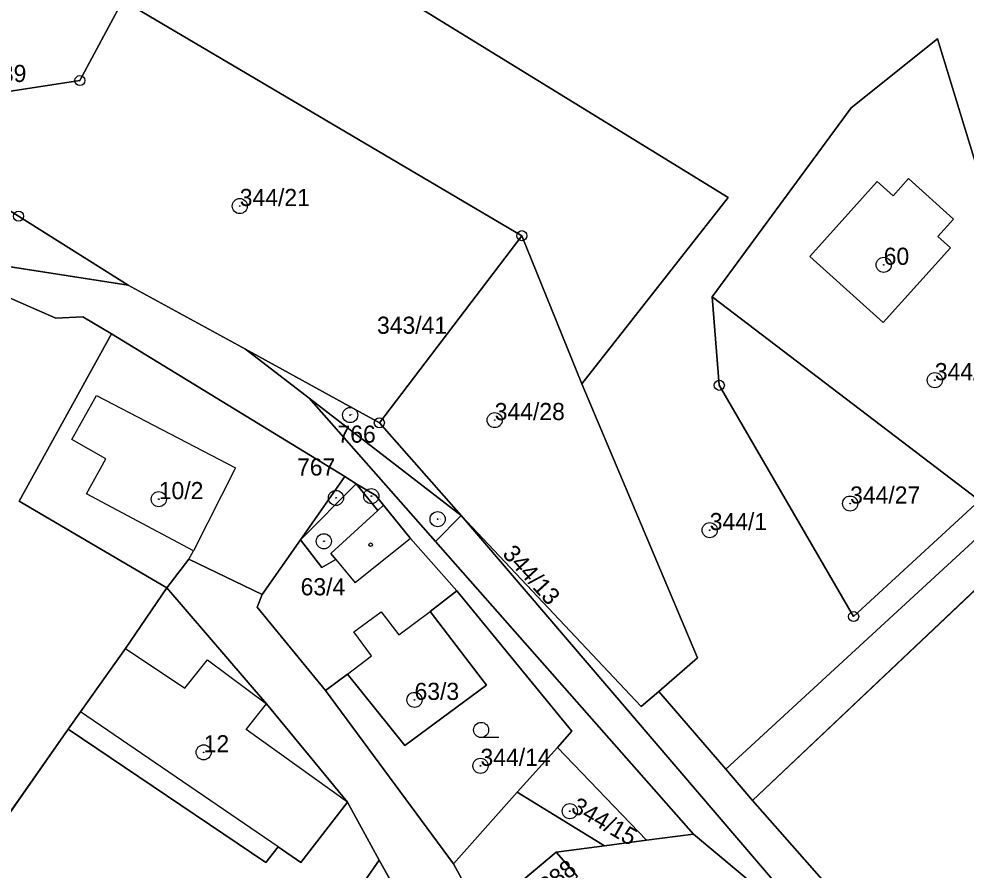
# Model space of a CAD drawing. Extents: x -652854 to -650068, y -1097661 to -1095417.
# Drawn here: x -650913.5 to -650819.6, y -1095946.2 to -1095861.8 of the extents above; entities that cross this region are included whole.
import ezdxf

# ---------------------------------------------------------------- set-up
doc = ezdxf.new("R2010")
doc.units = 0
for name, color, linetype in [('Definiční body parcel', 7, 'Continuous'), ('Geodetické body', 7, 'Continuous'), ('Hranice - vnitř_ kresba', 7, 'Continuous'), ('Hranice parcel', 7, 'Continuous'), ('Obvody jako plochy', 7, 'Continuous'), ('Parcelní čísla', 7, 'Continuous'), ('Prvky pro prodl_ par_ č_', 7, 'Continuous'), ('Značky kultur', 7, 'Continuous'), ('Značky na budově ne v SPI', 7, 'Continuous')]:
    doc.layers.add(name, color=color, linetype=linetype)

msp = doc.modelspace()

# ---------------------------------------------------------------- linework, layer by layer
at = {"layer": 'Definiční body parcel'}
for centre, radius in [((-650891.61, -1095880.33), 0.75), ((-650891.61, -1095880.33), 0.0327), ((-650827.76, -1095886.16), 0.75), ((-650827.76, -1095886.16), 0.0327), ((-650822.69, -1095897.6), 0.75), ((-650822.69, -1095897.6), 0.0327), ((-650880.66, -1095901.06), 0.75), ((-650880.66, -1095901.06), 0.0327), ((-650866.33, -1095901.56), 0.75), ((-650866.33, -1095901.56), 0.0327), ((-650899.64, -1095909.4), 0.75), ((-650882.07, -1095909.28), 0.75), ((-650878.57, -1095909.11), 0.75), ((-650899.64, -1095909.4), 0.0327), ((-650882.07, -1095909.28), 0.0327), ((-650878.57, -1095909.11), 0.0327), ((-650831.09, -1095909.84), 0.75), ((-650831.09, -1095909.84), 0.0327), ((-650871.99, -1095911.39), 0.75), ((-650871.99, -1095911.39), 0.0327), ((-650845.01, -1095912.47), 0.75), ((-650845.01, -1095912.47), 0.0327), ((-650883.27, -1095913.58), 0.75), ((-650883.27, -1095913.58), 0.0327), ((-650874.28, -1095929.31), 0.75), ((-650874.28, -1095929.31), 0.0327), ((-650895.19, -1095934.51), 0.75), ((-650895.19, -1095934.51), 0.0327), ((-650867.74, -1095935.85), 0.75), ((-650867.74, -1095935.85), 0.0327), ((-650858.88, -1095940.34), 0.75), ((-650858.88, -1095940.34), 0.0327)]:
    msp.add_circle(centre, radius, dxfattribs=at)
at = {"layer": 'Geodetické body'}
for centre, radius in [((-650907.46, -1095867.89), 0.5), ((-650907.46, -1095867.89), 0.001), ((-650913.54, -1095881.34), 0.5), ((-650863.63, -1095883.27), 0.5), ((-650863.63, -1095883.27), 0.001), ((-650844.06, -1095898.11), 0.5), ((-650844.06, -1095898.11), 0.001), ((-650877.77, -1095901.83), 0.5), ((-650877.77, -1095901.83), 0.001), ((-650830.74, -1095921.05), 0.5), ((-650830.74, -1095921.05), 0.001)]:
    msp.add_circle(centre, radius, dxfattribs=at)
at = {"layer": 'Hranice - vnitř_ kresba'}
for p, q in [((-650908.27, -1095903.48), (-650905.83, -1095899.12)), ((-650905.83, -1095899.12), (-650892.04, -1095906.3)), ((-650904.9, -1095905.4), (-650908.27, -1095903.48)), ((-650906.82, -1095908.86), (-650904.9, -1095905.4)), ((-650892.04, -1095906.3), (-650896.19, -1095914.54)), ((-650896.19, -1095914.54), (-650906.82, -1095908.86)), ((-650874.69, -1095913.31), (-650880.15, -1095917.7)), ((-650896.67, -1095915.35), (-650896.19, -1095914.54)), ((-650882.07, -1095915.4), (-650880.15, -1095917.7)), ((-650880.29, -1095922.55), (-650877.6, -1095920.56)), ((-650877.6, -1095920.56), (-650875.83, -1095922.87)), ((-650875.83, -1095922.87), (-650872.74, -1095920.53)), ((-650878.56, -1095924.94), (-650880.29, -1095922.55)), ((-650902.94, -1095924.22), (-650897.05, -1095928.13)), ((-650880.93, -1095926.76), (-650878.56, -1095924.94)), ((-650897.05, -1095928.13), (-650894.82, -1095925.34)), ((-650894.82, -1095925.34), (-650888.97, -1095929.69)), ((-650890.97, -1095932.24), (-650888.97, -1095929.69)), ((-650887.79, -1095943.89), (-650907.39, -1095930.49)), ((-650880.92, -1095939.45), (-650890.97, -1095932.24))]:
    msp.add_line(p, q, dxfattribs=at)
at = {"layer": 'Hranice parcel'}
for p, q in [((-650888.99, -1095851.28), (-650843.17, -1095879.48)), ((-650907.46, -1095867.89), (-650903.19, -1095859.94)), ((-650903.19, -1095859.94), (-650863.63, -1095883.27)), ((-650822.42, -1095863.74), (-650831, -1095870.58)), ((-650813.57, -1095892.69), (-650822.42, -1095863.74)), ((-650923.79, -1095870.4), (-650907.46, -1095867.89)), ((-650831, -1095870.58), (-650844.78, -1095889.35)), ((-650828.41, -1095877.9), (-650835.1, -1095885.33)), ((-650826.82, -1095879.31), (-650828.41, -1095877.9)), ((-650825.29, -1095877.6), (-650826.82, -1095879.31)), ((-650820.83, -1095881.62), (-650825.29, -1095877.6)), ((-650843.17, -1095879.48), (-650857.68, -1095897.96)), ((-650902.68, -1095888.18), (-650913.54, -1095881.34)), ((-650822.38, -1095883.34), (-650820.83, -1095881.62)), ((-650932.81, -1095883.5), (-650902.68, -1095888.18)), ((-650863.63, -1095883.27), (-650877.77, -1095901.83)), ((-650863.63, -1095883.27), (-650857.68, -1095897.96)), ((-650821.13, -1095884.46), (-650822.38, -1095883.34)), ((-650827.82, -1095891.89), (-650821.13, -1095884.46)), ((-650835.1, -1095885.33), (-650827.82, -1095891.89)), ((-650891.03, -1095894.51), (-650902.68, -1095888.18)), ((-650914.96, -1095889.2), (-650909.84, -1095891.45)), ((-650844.78, -1095889.35), (-650818.25, -1095909.52)), ((-650844.78, -1095889.35), (-650844.06, -1095898.11)), ((-650909.84, -1095891.45), (-650907.17, -1095891.31)), ((-650907.17, -1095891.31), (-650904.34, -1095892.99)), ((-650913.47, -1095909.59), (-650904.34, -1095892.99)), ((-650904.34, -1095892.99), (-650881.2, -1095907.17)), ((-650884.73, -1095899.4), (-650891.03, -1095894.51)), ((-650877.77, -1095901.83), (-650891.03, -1095894.51)), ((-650857.68, -1095897.96), (-650846.23, -1095925.14)), ((-650844.06, -1095898.11), (-650830.74, -1095921.05)), ((-650872.2, -1095913.61), (-650884.73, -1095899.4)), ((-650869.65, -1095911.01), (-650884.73, -1095899.4)), ((-650869.65, -1095911.01), (-650877.77, -1095901.83)), ((-650881.2, -1095907.17), (-650885.58, -1095913.43)), ((-650885.58, -1095913.43), (-650880.08, -1095907.88)), ((-650881.2, -1095907.17), (-650880.08, -1095907.88)), ((-650880.08, -1095907.88), (-650878.12, -1095909.05)), ((-650877.91, -1095910.51), (-650880.08, -1095907.88)), ((-650898.83, -1095918.21), (-650913.47, -1095909.59)), ((-650878.12, -1095909.05), (-650877.36, -1095910)), ((-650830.74, -1095921.05), (-650818.25, -1095909.52)), ((-650877.91, -1095910.51), (-650882.58, -1095914.79)), ((-650877.36, -1095910), (-650877.91, -1095910.51)), ((-650877.36, -1095910), (-650874.69, -1095913.31)), ((-650869.65, -1095911.01), (-650872.2, -1095913.61)), ((-650869.65, -1095911.01), (-650831.59, -1095955.54)), ((-650851.8, -1095929.96), (-650869.65, -1095911.01)), ((-650817.71, -1095912.52), (-650843.42, -1095936.19)), ((-650885.58, -1095913.43), (-650889.39, -1095918.87)), ((-650883.48, -1095916.17), (-650885.58, -1095913.43)), ((-650874.69, -1095913.31), (-650870.09, -1095918.48)), ((-650846.62, -1095942.61), (-650872.2, -1095913.61)), ((-650896.67, -1095915.35), (-650898.83, -1095918.21)), ((-650889.39, -1095918.87), (-650896.67, -1095915.35)), ((-650882.07, -1095915.4), (-650883.48, -1095916.17)), ((-650882.58, -1095914.79), (-650882.07, -1095915.4)), ((-650840.77, -1095939.29), (-650817.24, -1095917.02)), ((-650902.94, -1095924.22), (-650898.83, -1095918.21)), ((-650898.83, -1095918.21), (-650888.97, -1095929.69)), ((-650889.39, -1095918.87), (-650889.88, -1095920.1)), ((-650870.09, -1095918.48), (-650872.74, -1095920.53)), ((-650858.67, -1095932.4), (-650870.09, -1095918.48)), ((-650883.1, -1095928.38), (-650889.88, -1095920.1)), ((-650872.74, -1095920.53), (-650867.13, -1095927.84)), ((-650907.39, -1095930.49), (-650902.94, -1095924.22)), ((-650846.23, -1095925.14), (-650850.06, -1095928.49)), ((-650880.93, -1095926.76), (-650883.1, -1095928.38)), ((-650875.23, -1095933.84), (-650880.93, -1095926.76)), ((-650883.1, -1095928.38), (-650870.42, -1095945.56)), ((-650867.13, -1095927.84), (-650875.23, -1095933.84)), ((-650850.06, -1095928.49), (-650851.8, -1095929.96)), ((-650843.42, -1095936.19), (-650850.06, -1095928.49)), ((-650888.97, -1095929.69), (-650880.92, -1095939.45)), ((-650908.63, -1095932.22), (-650907.39, -1095930.49)), ((-650915.66, -1095942.26), (-650908.63, -1095932.22)), ((-650908.63, -1095932.22), (-650889.01, -1095945.42)), ((-650860.09, -1095934.02), (-650858.67, -1095932.4)), ((-650864.09, -1095938.47), (-650860.09, -1095934.02)), ((-650851.27, -1095943.21), (-650860.09, -1095934.02)), ((-650843.42, -1095936.19), (-650840.77, -1095939.29)), ((-650870.42, -1095945.56), (-650864.09, -1095938.47)), ((-650855.44, -1095943.79), (-650864.09, -1095938.47)), ((-650885.57, -1095945.44), (-650880.92, -1095939.45)), ((-650877.8, -1095945.22), (-650880.92, -1095939.45)), ((-650840.77, -1095939.29), (-650828.97, -1095952.68)), ((-650846.62, -1095942.61), (-650851.27, -1095943.21)), ((-650838.15, -1095949.69), (-650846.62, -1095942.61)), ((-650855.44, -1095943.79), (-650860.23, -1095944.4)), ((-650851.27, -1095943.21), (-650855.44, -1095943.79)), ((-650889.01, -1095945.42), (-650887.79, -1095943.89)), ((-650887.79, -1095943.89), (-650885.57, -1095945.44)), ((-650860.23, -1095944.4), (-650865.44, -1095948.76)), ((-650860.23, -1095944.4), (-650858.12, -1095946.81)), ((-650906.97, -1095987.24), (-650877.8, -1095945.22)), ((-650865.79, -1095966.45), (-650877.8, -1095945.22)), ((-650864, -1095957.32), (-650870.42, -1095945.56))]:
    msp.add_line(p, q, dxfattribs=at)
at = {"layer": 'Obvody jako plochy'}
for points in [[(-650822.33, -1095847.63), (-650821.45, -1095812.61), (-650825.74, -1095811.08), (-650838.32, -1095807.2), (-650848.05, -1095802.48), (-650850.5, -1095805.49), (-650871.31, -1095836.39), (-650885.3, -1095832.78), (-650888.99, -1095851.28), (-650843.17, -1095879.48), (-650857.68, -1095897.96), (-650846.23, -1095925.14), (-650850.06, -1095928.49), (-650843.42, -1095936.19), (-650817.71, -1095912.52), (-650794.81, -1095896.6), (-650798.62, -1095890.09), (-650802.65, -1095884.5), (-650812.74, -1095871.62), (-650816.62, -1095864.78), (-650818.61, -1095859.41)], [(-650950.21, -1095830.99), (-650955.12, -1095851.96), (-650946.14, -1095855.5), (-650934.64, -1095858.09), (-650925.55, -1095861.88), (-650927.79, -1095867.74), (-650923.79, -1095870.4), (-650907.46, -1095867.89), (-650903.19, -1095859.94), (-650863.63, -1095883.27), (-650857.68, -1095897.96), (-650843.17, -1095879.48), (-650888.99, -1095851.28), (-650885.3, -1095832.78), (-650897.08, -1095826.41), (-650916.2, -1095812.16), (-650931.45, -1095804.19)], [(-650926.99, -1095870.8), (-650927, -1095872.87), (-650913.54, -1095881.34), (-650902.68, -1095888.18), (-650891.03, -1095894.51), (-650877.77, -1095901.83), (-650863.63, -1095883.27), (-650903.19, -1095859.94), (-650907.46, -1095867.89), (-650923.79, -1095870.4)], [(-650830.74, -1095921.05), (-650844.06, -1095898.11), (-650844.78, -1095889.35), (-650831, -1095870.58), (-650822.42, -1095863.74), (-650813.57, -1095892.69), (-650813.78, -1095904.48), (-650818.25, -1095909.52)], [(-650844.78, -1095889.35), (-650818.25, -1095909.52), (-650813.78, -1095904.48), (-650813.57, -1095892.69), (-650822.42, -1095863.74), (-650831, -1095870.58)], [(-650931.56, -1095881.13), (-650932.81, -1095883.5), (-650902.68, -1095888.18), (-650913.54, -1095881.34), (-650927, -1095872.87)], [(-650835.1, -1095885.33), (-650827.82, -1095891.89), (-650821.13, -1095884.46), (-650822.38, -1095883.34), (-650820.83, -1095881.62), (-650825.29, -1095877.6), (-650826.82, -1095879.31), (-650828.41, -1095877.9)], [(-650835.1, -1095885.33), (-650828.41, -1095877.9), (-650826.82, -1095879.31), (-650825.29, -1095877.6), (-650820.83, -1095881.62), (-650822.38, -1095883.34), (-650821.13, -1095884.46), (-650827.82, -1095891.89)], [(-650863.63, -1095883.27), (-650877.77, -1095901.83), (-650869.65, -1095911.01), (-650851.8, -1095929.96), (-650850.06, -1095928.49), (-650846.23, -1095925.14), (-650857.68, -1095897.96)], [(-650914.96, -1095889.2), (-650924.87, -1095890.09), (-650962.32, -1095886.47), (-650977.45, -1095885.85), (-650984.48, -1095883.78), (-650991.01, -1095904.42), (-650915.66, -1095942.26), (-650908.63, -1095932.22), (-650907.39, -1095930.49), (-650902.94, -1095924.22), (-650898.83, -1095918.21), (-650913.47, -1095909.59), (-650904.34, -1095892.99), (-650907.17, -1095891.31), (-650909.84, -1095891.45)], [(-650830.74, -1095921.05), (-650818.25, -1095909.52), (-650844.78, -1095889.35), (-650844.06, -1095898.11)], [(-650885.58, -1095913.43), (-650881.2, -1095907.17), (-650904.34, -1095892.99), (-650913.47, -1095909.59), (-650898.83, -1095918.21), (-650896.67, -1095915.35), (-650889.39, -1095918.87)], [(-650877.77, -1095901.83), (-650891.03, -1095894.51), (-650884.73, -1095899.4), (-650869.65, -1095911.01)], [(-650869.65, -1095911.01), (-650884.73, -1095899.4), (-650872.2, -1095913.61)], [(-650881.2, -1095907.17), (-650885.58, -1095913.43), (-650880.08, -1095907.88)], [(-650877.91, -1095910.51), (-650880.08, -1095907.88), (-650885.58, -1095913.43), (-650883.48, -1095916.17), (-650882.07, -1095915.4), (-650882.58, -1095914.79)], [(-650878.12, -1095909.05), (-650880.08, -1095907.88), (-650877.91, -1095910.51), (-650877.36, -1095910)], [(-650867.13, -1095927.84), (-650872.74, -1095920.53), (-650870.09, -1095918.48), (-650874.69, -1095913.31), (-650877.36, -1095910), (-650877.91, -1095910.51), (-650882.58, -1095914.79), (-650882.07, -1095915.4), (-650883.48, -1095916.17), (-650885.58, -1095913.43), (-650889.39, -1095918.87), (-650889.88, -1095920.1), (-650883.1, -1095928.38), (-650880.93, -1095926.76), (-650875.23, -1095933.84)], [(-650839.47, -1095951.17), (-650833.55, -1095958.46), (-650767.4, -1095990.09), (-650750.01, -1095996.81), (-650760.98, -1095990.15), (-650831.59, -1095955.54), (-650869.65, -1095911.01), (-650872.2, -1095913.61), (-650846.62, -1095942.61), (-650838.15, -1095949.69)], [(-650861.2, -1095966.88), (-650864, -1095957.32), (-650870.42, -1095945.56), (-650883.1, -1095928.38), (-650889.88, -1095920.1), (-650889.39, -1095918.87), (-650896.67, -1095915.35), (-650898.83, -1095918.21), (-650888.97, -1095929.69), (-650880.92, -1095939.45), (-650877.8, -1095945.22), (-650865.79, -1095966.45), (-650861.57, -1096000.28), (-650869.83, -1096021.1), (-650866.08, -1096025.56), (-650856.19, -1096001.44), (-650856.25, -1095986.12)], [(-650898.83, -1095918.21), (-650902.94, -1095924.22), (-650907.39, -1095930.49), (-650908.63, -1095932.22), (-650889.01, -1095945.42), (-650887.79, -1095943.89), (-650885.57, -1095945.44), (-650880.92, -1095939.45), (-650888.97, -1095929.69)], [(-650867.13, -1095927.84), (-650875.23, -1095933.84), (-650880.93, -1095926.76), (-650883.1, -1095928.38), (-650870.42, -1095945.56), (-650864.09, -1095938.47), (-650860.09, -1095934.02), (-650858.67, -1095932.4), (-650870.09, -1095918.48), (-650872.74, -1095920.53)], [(-650919.07, -1095983.1), (-650906.97, -1095987.24), (-650877.8, -1095945.22), (-650880.92, -1095939.45), (-650885.57, -1095945.44), (-650887.79, -1095943.89), (-650889.01, -1095945.42), (-650908.63, -1095932.22), (-650915.66, -1095942.26), (-650939.79, -1095976.94)], [(-650855.44, -1095943.79), (-650851.27, -1095943.21), (-650860.09, -1095934.02), (-650864.09, -1095938.47)], [(-650852.46, -1095962.14), (-650847.56, -1095957.86), (-650842.35, -1095953.5), (-650839.47, -1095951.17), (-650838.15, -1095949.69), (-650846.62, -1095942.61), (-650851.27, -1095943.21), (-650855.44, -1095943.79), (-650860.23, -1095944.4), (-650858.12, -1095946.81), (-650862.98, -1095951.3)], [(-650860.23, -1095944.4), (-650865.44, -1095948.76), (-650862.98, -1095951.3), (-650858.12, -1095946.81)], [(-650869.83, -1096021.1), (-650861.57, -1096000.28), (-650865.79, -1095966.45), (-650877.8, -1095945.22), (-650906.97, -1095987.24), (-650888.72, -1095999.9), (-650884.15, -1096004.16), (-650878.58, -1096010.13)]]:
    msp.add_lwpolyline(points, close=True, dxfattribs=at)
for points in [[(-650914.96, -1095889.2), (-650909.84, -1095891.45), (-650907.17, -1095891.31), (-650904.34, -1095892.99), (-650881.2, -1095907.17), (-650880.08, -1095907.88), (-650878.12, -1095909.05), (-650877.36, -1095910), (-650874.69, -1095913.31), (-650870.09, -1095918.48), (-650858.67, -1095932.4), (-650860.09, -1095934.02), (-650851.27, -1095943.21), (-650846.62, -1095942.61), (-650872.2, -1095913.61), (-650884.73, -1095899.4), (-650891.03, -1095894.51), (-650902.68, -1095888.18), (-650932.81, -1095883.5)], [(-650768.13, -1095982), (-650828.97, -1095952.68), (-650840.77, -1095939.29), (-650843.42, -1095936.19), (-650850.06, -1095928.49), (-650851.8, -1095929.96), (-650869.65, -1095911.01), (-650831.59, -1095955.54), (-650760.98, -1095990.15)], [(-650817.71, -1095912.52), (-650843.42, -1095936.19), (-650840.77, -1095939.29), (-650817.24, -1095917.02)], [(-650817.24, -1095917.02), (-650840.77, -1095939.29), (-650828.97, -1095952.68), (-650768.13, -1095982)], [(-650766.86, -1095994.47), (-650835.62, -1095960.85), (-650842.35, -1095953.5), (-650847.56, -1095957.86), (-650852.46, -1095962.14), (-650862.98, -1095951.3), (-650865.44, -1095948.76), (-650860.23, -1095944.4), (-650855.44, -1095943.79), (-650864.09, -1095938.47), (-650870.42, -1095945.56), (-650864, -1095957.32), (-650861.2, -1095966.88), (-650854.5, -1095965.91), (-650844.61, -1095959.76), (-650830.01, -1095970.16), (-650818.08, -1095980.3)]]:
    msp.add_lwpolyline(points, dxfattribs=at)
at = {"layer": 'Značky kultur'}
msp.add_line((-650865.93, -1095933.04), (-650867.68, -1095933.04), dxfattribs=at)
msp.add_circle((-650867.68, -1095932.29), 0.75, dxfattribs=at)
at = {"layer": 'Značky na budově ne v SPI'}
msp.add_circle((-650878.63, -1095913.92), 0.175, dxfattribs=at)

# ---------------------------------------------------------------- texts
at = {"layer": 'Parcelní čísla'}
for s, height, p in [('344/21', 1.7, (-650891.61, -1095880.33)), ('60', 1.7, (-650827.76, -1095886.16)), ('344/19', 1.7, (-650822.69, -1095897.6)), ('344/28', 1.7, (-650866.33, -1095901.56)), ('343/41', 0.1, (-650880.66, -1095901.06)), ('10/2', 1.7, (-650899.64, -1095909.4)), ('344/27', 1.7, (-650831.09, -1095909.84)), ('766', 0.1, (-650878.57, -1095909.11)), ('767', 0.1, (-650882.07, -1095909.28)), ('344/1', 1.7, (-650845.01, -1095912.47)), ('344/13', 0.1, (-650871.99, -1095911.39)), ('63/4', 0.1, (-650883.27, -1095913.58)), ('63/3', 1.7, (-650874.28, -1095929.31)), ('12', 1.7, (-650895.19, -1095934.51)), ('344/14', 1.7, (-650867.74, -1095935.85))]:
    msp.add_text(s, height=height, dxfattribs=at).set_placement(p)
for s, rotation, p in [('344/15', 329.895, (-650858.88, -1095940.34)), ('388', 37.116, (-650861.12, -1095948.68))]:
    msp.add_text(s, height=1.7, rotation=rotation, dxfattribs=at).set_placement(p)
at = {"layer": 'Prvky pro prodl_ par_ č_'}
for s, p in [('343/39', (-650919.72, -1095868.03)), ('343/41', (-650878, -1095893)), ('766', (-650881.92, -1095903.8)), ('767', (-650885.93, -1095907.06)), ('63/4', (-650885.574, -1095918.94))]:
    msp.add_text(s, height=1.7, dxfattribs=at).set_placement(p)
msp.add_text('344/13', height=1.7, rotation=312.264, dxfattribs=at).set_placement((-650865.642, -1095914.897))

doc.saveas('drawing.dxf')
